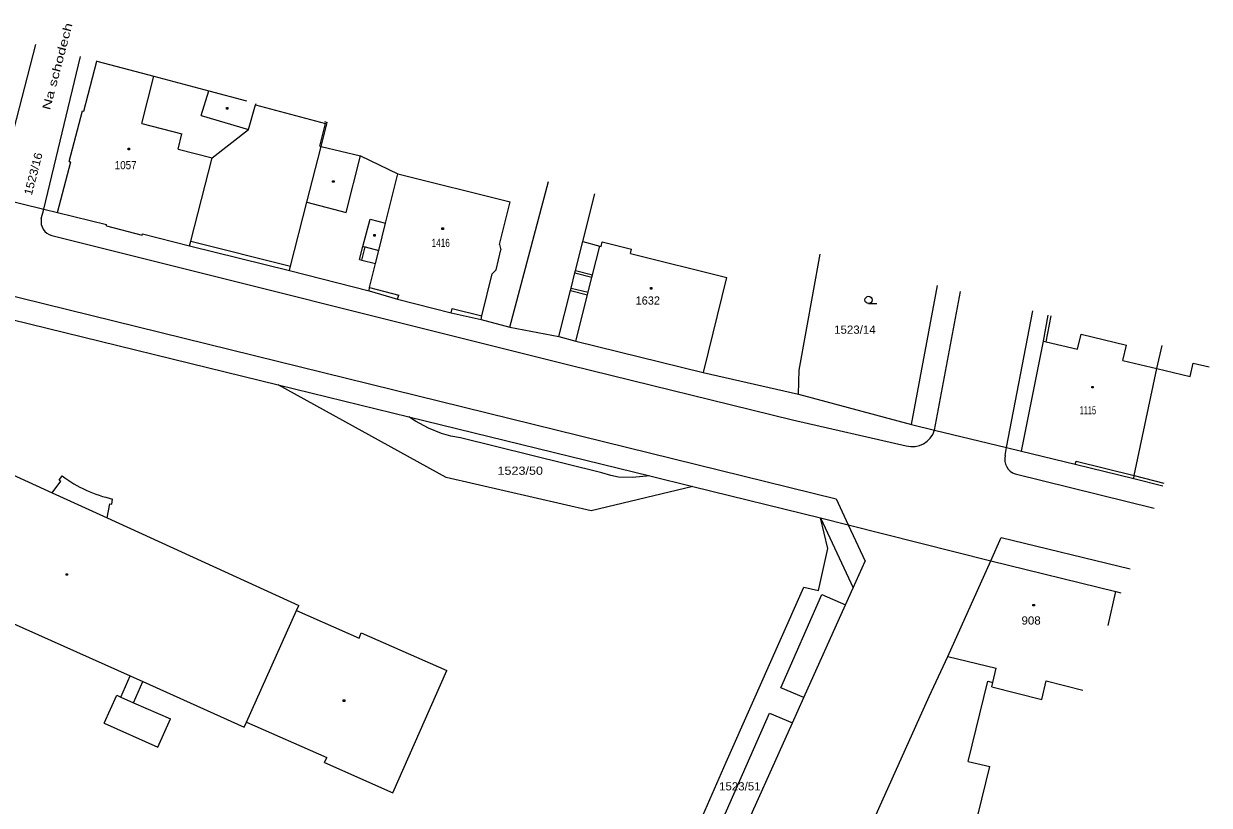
# Model space of a CAD drawing. Extents: x -630464 to -630140, y -1004543 to -1004208.
# Drawn here: x -630262.9 to -630139.7, y -1004346.3 to -1004265.1 of the extents above; entities that cross this region are included whole.
import ezdxf

# ---------------------------------------------------------------- set-up
doc = ezdxf.new("R2010")
doc.units = 0
doc.header["$LTSCALE"] = 0.34
for name, color, linetype, lineweight in [('1', 7, 'Continuous', 13), ('2', 7, 'Continuous', 13), ('23', 7, 'Continuous', 13), ('25', 7, 'Continuous', 13)]:
    doc.layers.add(name, color=color, linetype=linetype, lineweight=lineweight)
for name, color, linetype in [('14', 7, 'Continuous'), ('15', 7, 'Continuous'), ('38', 7, 'Continuous')]:
    doc.layers.add(name, color=color, linetype=linetype)

msp = doc.modelspace()

# ---------------------------------------------------------------- linework, layer by layer
at = {"layer": '1'}
for p, q in [((-630255.33, -1004268.95), (-630255.325, -1004268.931)), ((-630249.39, -1004270.53), (-630243.68, -1004272.05)), ((-630243.68, -1004272.05), (-630239.756, -1004273.091)), ((-630232.02, -1004277.84), (-630231.38, -1004275.33)), ((-630231.66, -1004275.255), (-630231.38, -1004275.33)), ((-630231.38, -1004275.33), (-630231.38, -1004275.329)), ((-630259.41, -1004284.68), (-630258.04, -1004279.42)), ((-630258.19, -1004279.38), (-630258.04, -1004279.42)), ((-630212.41, -1004296.61), (-630208.38, -1004281.476)), ((-630204.81, -1004287.72), (-630203.562, -1004282.763)), ((-630213.46, -1004288.02), (-630212.36, -1004283.6)), ((-630254.34, -1004286.1), (-630254.31, -1004285.96)), ((-630213.46, -1004288.02), (-630213.33, -1004288.59)), ((-630199.86, -1004288.97), (-630199.74, -1004288.51)), ((-630199.86, -1004288.97), (-630189.85, -1004291.45)), ((-630182.31, -1004301.07), (-630180.14, -1004289.023)), ((-630235.31, -1004290.72), (-630227.03, -1004292.85)), ((-630170.66, -1004306.74), (-630167.959, -1004292.278)), ((-630156.94, -1004298.06), (-630156.431, -1004295.358)), ((-630264.17, -1004295.83), (-630236.47, -1004302.62)), ((-630159.2, -1004309.52), (-630156.94, -1004298.06)), ((-630145.13, -1004300.92), (-630144.594, -1004298.522)), ((-630182.39, -1004303.59), (-630182.31, -1004301.07)), ((-630259.25, -1004312.51), (-630258.94, -1004312.08)), ((-630259.25, -1004312.51), (-630259.08, -1004312.63)), ((-630147.55, -1004312.35), (-630144.524, -1004313.103)), ((-630193.37, -1004313.18), (-630180.1, -1004316.43)), ((-630254.25, -1004316.43), (-630234.34, -1004325.54)), ((-630180.1, -1004316.43), (-630176.7, -1004323.71)), ((-630285.12, -1004317.98), (-630251.86, -1004332.87)), ((-630166.88, -1004330.85), (-630162.41, -1004320.9)), ((-630162.41, -1004320.9), (-630149.39, -1004324.1)), ((-630234.57, -1004326.06), (-630234.34, -1004325.54)), ((-630234.57, -1004326.06), (-630228.07, -1004328.93)), ((-630251.86, -1004332.87), (-630250.54, -1004333.46)), ((-630250.54, -1004333.46), (-630240, -1004338.18)), ((-630231.67, -1004341.88), (-630231.43, -1004341.34))]:
    msp.add_line(p, q, dxfattribs=at)
for points in [[(-630258.19, -1004279.38), (-630256.82, -1004274.12), (-630256.68, -1004274.16), (-630255.33, -1004268.95), (-630249.39, -1004270.53)], [(-630300.16, -1004274.67), (-630288.74, -1004277.5), (-630277.71, -1004280.2), (-630267.19, -1004282.8), (-630265.79, -1004283.15), (-630260.85, -1004284.35), (-630259.41, -1004284.68), (-630254.31, -1004285.96)], [(-630233.49, -1004283.64), (-630232.02, -1004277.84), (-630227.92, -1004278.8), (-630224.05, -1004280.69), (-630212.36, -1004283.6)], [(-630235.31, -1004290.72), (-630235.2, -1004290.27), (-630233.49, -1004283.64)], [(-630254.34, -1004286.1), (-630250.61, -1004287.04), (-630250.58, -1004286.91), (-630245.68, -1004288.15), (-630235.31, -1004290.72)], [(-630207.29, -1004297.59), (-630206.09, -1004292.81), (-630206.03, -1004292.57), (-630205.63, -1004290.98), (-630205.57, -1004290.74), (-630204.81, -1004287.72), (-630203.05, -1004288.18), (-630202.91, -1004288.22), (-630202.79, -1004287.75), (-630199.74, -1004288.51)], [(-630215.38, -1004295.83), (-630215.31, -1004295.43), (-630214.22, -1004291.07), (-630213.81, -1004290.65), (-630213.33, -1004288.59)], [(-630192.3, -1004301.34), (-630192.25, -1004301.18), (-630189.85, -1004291.45)], [(-630227.03, -1004292.85), (-630224.06, -1004293.71), (-630218.5, -1004295.11), (-630215.38, -1004295.83), (-630212.41, -1004296.61), (-630207.29, -1004297.59), (-630205.54, -1004298.07), (-630192.3, -1004301.34), (-630182.39, -1004303.59), (-630170.66, -1004306.74), (-630168.25, -1004307.33), (-630160.76, -1004309.14), (-630159.2, -1004309.52), (-630153.62, -1004310.85), (-630147.55, -1004312.35)], [(-630147.55, -1004312.35), (-630147.49, -1004312.05), (-630145.13, -1004300.92)], [(-630193.37, -1004313.18), (-630203.93, -1004315.72), (-630219.03, -1004312.26), (-630236.47, -1004302.62)], [(-630236.47, -1004302.62), (-630222.91, -1004305.94), (-630197.86, -1004312.08), (-630193.37, -1004313.18)], [(-630279.59, -1004304.85), (-630259.96, -1004313.83), (-630259.08, -1004312.63)], [(-630254.25, -1004316.43), (-630253.99, -1004314.97), (-630253.78, -1004315.01), (-630253.69, -1004314.48)], [(-630199.97, -1004375.5), (-630203.94, -1004373.79), (-630197.92, -1004360.13), (-630189.91, -1004341.84), (-630181.84, -1004323.63), (-630180.31, -1004323.98), (-630179.33, -1004319.62), (-630180.1, -1004316.43)], [(-630180.1, -1004316.43), (-630177.23, -1004317.15), (-630162.41, -1004320.9)], [(-630206.18, -1004389.32), (-630199.97, -1004375.5), (-630198.73, -1004372.73), (-630195.8, -1004366.22), (-630194.2, -1004362.66), (-630190.16, -1004353.66), (-630188.86, -1004350.78), (-630183.01, -1004337.75), (-630181.83, -1004335.12), (-630177.5, -1004325.49), (-630176.7, -1004323.71)], [(-630150.197, -1004327.613), (-630149.39, -1004324.1), (-630148.873, -1004324.226)], [(-630228.07, -1004328.93), (-630227.84, -1004328.39), (-630218.96, -1004332.31)], [(-630177.89, -1004355.21), (-630168.8, -1004335), (-630166.88, -1004330.85)], [(-630231.67, -1004341.88), (-630224.57, -1004345.02), (-630218.96, -1004332.31)], [(-630240, -1004338.18), (-630239.76, -1004337.66), (-630231.43, -1004341.34)]]:
    msp.add_lwpolyline(points, dxfattribs=at)
msp.add_arc((-630250.699, -1004300.994), 13.814, 233.37226, 257.49339, dxfattribs=at)
at = {"layer": '2'}
for p, q in [((-630265.79, -1004283.15), (-630261.682, -1004267.232)), ((-630260.85, -1004284.35), (-630257.025, -1004268.476)), ((-630250.66, -1004275.43), (-630249.39, -1004270.53)), ((-630244.47, -1004274.63), (-630243.68, -1004272.05)), ((-630243.68, -1004272.05), (-630243.678, -1004272.043)), ((-630238.82, -1004273.49), (-630238.78, -1004273.352)), ((-630244.47, -1004274.63), (-630239.58, -1004276.07)), ((-630250.66, -1004275.43), (-630246.48, -1004276.52)), ((-630232.16, -1004277.81), (-630231.56, -1004275.44)), ((-630246.89, -1004278.11), (-630246.48, -1004276.52)), ((-630243.34, -1004279.03), (-630239.58, -1004276.07)), ((-630246.89, -1004278.11), (-630243.34, -1004279.03)), ((-630232.16, -1004277.81), (-630232.02, -1004277.84)), ((-630245.56, -1004287.69), (-630243.34, -1004279.03)), ((-630229.41, -1004284.68), (-630227.92, -1004278.8)), ((-630303.66, -1004283.61), (-630178.49, -1004314.45)), ((-630261.1, -1004285.36), (-630260.85, -1004284.35)), ((-630233.49, -1004283.64), (-630229.41, -1004284.68)), ((-630227.68, -1004288.22), (-630226.91, -1004285.4)), ((-630226.91, -1004285.4), (-630225.33, -1004285.8)), ((-630260.01, -1004287.1), (-630206.13, -1004300.58)), ((-630228.02, -1004289.58), (-630227.68, -1004288.22)), ((-630227.68, -1004288.22), (-630227.44, -1004288.28)), ((-630227.44, -1004288.28), (-630226.03, -1004288.63)), ((-630227.78, -1004289.64), (-630226.37, -1004289.99)), ((-630227, -1004292.51), (-630226.37, -1004289.99)), ((-630205.63, -1004290.98), (-630203.86, -1004291.41)), ((-630205.57, -1004290.74), (-630203.8, -1004291.17)), ((-630206.09, -1004292.81), (-630204.32, -1004293.24)), ((-630206.03, -1004292.57), (-630204.26, -1004292.99)), ((-630168.25, -1004307.33), (-630165.55, -1004292.921)), ((-630224.06, -1004293.71), (-630223.95, -1004293.28)), ((-630160.76, -1004309.14), (-630158.043, -1004294.928)), ((-630156.65, -1004298.13), (-630156.141, -1004295.436)), ((-630148.68, -1004300.07), (-630148.3, -1004298.49)), ((-630148.68, -1004300.07), (-630145.13, -1004300.92)), ((-630141.37, -1004300.35), (-630139.693, -1004300.746)), ((-630206.13, -1004300.58), (-630183.02, -1004306.26)), ((-630183.02, -1004306.26), (-630171.19, -1004308.94)), ((-630160.91, -1004309.97), (-630160.76, -1004309.14)), ((-630159.86, -1004311.87), (-630145.428, -1004315.415)), ((-630147.49, -1004312.05), (-630144.413, -1004312.819)), ((-630259.96, -1004313.83), (-630254.25, -1004316.43)), ((-630162.41, -1004320.9), (-630161.32, -1004318.49)), ((-630161.32, -1004318.49), (-630147.905, -1004321.75)), ((-630176.7, -1004323.71), (-630175.46, -1004320.94)), ((-630239.76, -1004337.66), (-630234.57, -1004326.06)), ((-630166.88, -1004330.85), (-630161.85, -1004332.07)), ((-630162.2, -1004333.56), (-630161.85, -1004332.07)), ((-630252.84, -1004335.06), (-630251.86, -1004332.87)), ((-630251.52, -1004335.65), (-630250.54, -1004333.46)), ((-630164.75, -1004341.75), (-630162.72, -1004333.43)), ((-630162.72, -1004333.43), (-630162.2, -1004333.56)), ((-630162.31, -1004334.01), (-630162.2, -1004333.56)), ((-630157.11, -1004335.32), (-630156.65, -1004333.37)), ((-630156.65, -1004333.37), (-630152.824, -1004334.332)), ((-630254.56, -1004337.79), (-630253.25, -1004334.87)), ((-630162.31, -1004334.01), (-630157.11, -1004335.32)), ((-630251.52, -1004335.65), (-630247.67, -1004337.34)), ((-630248.99, -1004340.29), (-630247.67, -1004337.34)), ((-630254.56, -1004337.79), (-630248.99, -1004340.29)), ((-630166.4, -1004358.22), (-630162.52, -1004342.29)), ((-630164.75, -1004341.75), (-630162.52, -1004342.29))]:
    msp.add_line(p, q, dxfattribs=at)
for points in [[(-630239.58, -1004276.07), (-630238.82, -1004273.49), (-630231.56, -1004275.44)], [(-630226.37, -1004289.99), (-630226.03, -1004288.63), (-630225.33, -1004285.8), (-630224.05, -1004280.69)], [(-630245.68, -1004288.15), (-630245.56, -1004287.69), (-630235.2, -1004290.27)], [(-630205.54, -1004298.07), (-630204.32, -1004293.24), (-630204.26, -1004292.99), (-630203.86, -1004291.41), (-630203.8, -1004291.17), (-630203.05, -1004288.18)], [(-630228.02, -1004289.58), (-630227.78, -1004289.64), (-630227.44, -1004288.28)], [(-630227.03, -1004292.85), (-630227, -1004292.51), (-630223.95, -1004293.28)], [(-630218.5, -1004295.11), (-630218.39, -1004294.66), (-630215.31, -1004295.43)], [(-630153.39, -1004298.91), (-630153.01, -1004297.36), (-630148.3, -1004298.49)], [(-630156.94, -1004298.06), (-630156.65, -1004298.13), (-630153.39, -1004298.91)], [(-630145.13, -1004300.92), (-630141.69, -1004301.73), (-630141.37, -1004300.35)], [(-630197.86, -1004312.08), (-630199.66, -1004312.24), (-630201.12, -1004312.2), (-630201.89, -1004312.05), (-630202.85, -1004311.76), (-630217.53, -1004308.11), (-630218.52, -1004307.95), (-630219.49, -1004307.66), (-630220.84, -1004307.12), (-630222.19, -1004306.4), (-630222.91, -1004305.94)], [(-630153.62, -1004310.85), (-630153.54, -1004310.55), (-630147.49, -1004312.05)], [(-630178.49, -1004314.45), (-630177.23, -1004317.15), (-630175.46, -1004320.94)], [(-630181.83, -1004335.12), (-630184.24, -1004334.12), (-630179.96, -1004324.4), (-630177.5, -1004325.49)], [(-630253.25, -1004334.87), (-630252.84, -1004335.06), (-630251.52, -1004335.65)], [(-630188.86, -1004350.78), (-630191.17, -1004349.81), (-630185.4, -1004336.73), (-630183.01, -1004337.75)]]:
    msp.add_lwpolyline(points, dxfattribs=at)
for centre, radius, start, end in [((-630259.627, -1004285.649), 1.501, 168.91752, 255.21156), ((-630170.553, -1004306.614), 2.412, 254.68088, 342.73102), ((-630159.342, -1004310.343), 1.612, 166.60152, 251.25133)]:
    msp.add_arc(centre, radius, start, end, dxfattribs=at)
at = {"layer": '23'}
msp.add_line((-630175.11, -1004294.16), (-630174.235, -1004294.16), dxfattribs=at)
msp.add_circle((-630175.11, -1004293.785), 0.375, dxfattribs=at)
at = {"layer": '25'}
for points in [[(-630241.86, -1004273.8), (-630241.71, -1004273.8), (-630241.71, -1004273.95), (-630241.86, -1004273.95)], [(-630252.07, -1004278.02), (-630251.92, -1004278.02), (-630251.92, -1004278.17), (-630252.07, -1004278.17)], [(-630230.82, -1004281.41), (-630230.67, -1004281.41), (-630230.67, -1004281.56), (-630230.82, -1004281.56)], [(-630219.46, -1004286.3), (-630219.31, -1004286.3), (-630219.31, -1004286.45), (-630219.46, -1004286.45)], [(-630226.54, -1004286.99), (-630226.39, -1004286.99), (-630226.39, -1004287.14), (-630226.54, -1004287.14)], [(-630197.78, -1004292.5), (-630197.63, -1004292.5), (-630197.63, -1004292.65), (-630197.78, -1004292.65)], [(-630151.9, -1004302.77), (-630151.75, -1004302.77), (-630151.75, -1004302.92), (-630151.9, -1004302.92)], [(-630258.52, -1004322.25), (-630258.37, -1004322.25), (-630258.37, -1004322.4), (-630258.52, -1004322.4)], [(-630158.02, -1004325.43), (-630157.87, -1004325.43), (-630157.87, -1004325.58), (-630158.02, -1004325.58)], [(-630229.71, -1004335.36), (-630229.56, -1004335.36), (-630229.56, -1004335.51), (-630229.71, -1004335.51)]]:
    msp.add_lwpolyline(points, close=True, dxfattribs=at)

# ---------------------------------------------------------------- texts
at = {"layer": '14', "width": 1.1}
msp.add_text('1523/16', height=0.85, rotation=75.515, dxfattribs=at).set_placement((-630262.09, -1004282.97))
at = {"layer": '14'}
for s, width, p in [('1523/14', 1.05, (-630178.69, -1004297.3)), ('1523/50', 1.15, (-630213.681, -1004311.96)), ('1523/51', 1.05, (-630190.652, -1004344.77))]:
    msp.add_text(s, height=0.85, dxfattribs=dict(at, width=width)).set_placement(p)
at = {"layer": '15'}
for s, width, p in [('1057', 0.9, (-630253.47, -1004280.2)), ('1416', 0.75, (-630220.53, -1004288.28)), ('1115', 0.65, (-630153.16, -1004305.68)), ('908', 1.05, (-630159.21, -1004327.53))]:
    msp.add_text(s, height=0.85, dxfattribs=dict(at, width=width)).set_placement(p)
msp.add_text('1632', height=0.85, dxfattribs=at).set_placement((-630199.32, -1004294.27))
at = {"layer": '38', "width": 1.4}
msp.add_text('Na schodech', height=0.85, rotation=75.316, dxfattribs=at).set_placement((-630260.2, -1004274.1))

doc.saveas('drawing.dxf')
